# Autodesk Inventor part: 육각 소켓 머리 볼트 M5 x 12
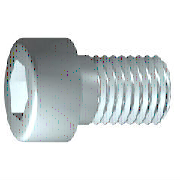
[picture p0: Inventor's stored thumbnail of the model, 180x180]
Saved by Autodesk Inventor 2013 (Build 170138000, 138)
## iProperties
IsCustomPart: 1
Created: 2012-02
Part Number: 육각 소켓 머리 볼트 M5 x 12
Material: 스테인리스강
Description: 6각 소켓 머리 캡 나사
Document SubType Name: Modeling
Standard: ISO 4762
Designer: mdu-01
Standard Revision: Fourth edition 2004-03-01
Standards Organization: ISO
Language: ko-KR
Size Designation: M5 x 12
Categories: <MemberInstance><Categories><Category DisplayName="조임쇠" InternalName="e4da775c-781d-43d5-af7c-5136215cf5a6" Mnemonic="FSTN"><Category DisplayName="볼트" InternalN
Density: 7.75 g/cm^3
Author: mdu-01
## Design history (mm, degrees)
sketch "스케치1"
  geometry: L1 (-1.167, 0)-(12, 0); L2 (12, 0)-(12, 2.5); L3 (12, 2.5)-(2, 2.5); L4 (2, 2.5)-(1.509, 2.5); L5 (1.509, 2.5)-(0, 2.5); L6 (0, 2.5)-(0, 4.25); L7 (0, 4.25)-(-5, 4.25); L8 (-5, 4.25)-(-5, 2.309); L9 (-5, 2.309)-(-2.5, 2.309); L10 (-2.5, 2.309)-(-1.167, 0); L11 (-8.4, 0)-(15.4, 0) reference; L12 (0, -0.85)-(0, 5.1) reference; L13 (2, 2.5)-(0, 2.5)
  constraints: 22 end point, 6 parallel, 2 collinear, 2 perpendicular, 1 horizontal, 1 point on line
  dimensions: "d1" = 10 distance from line of L3.end L2 (= GEL); "d2" = 0.49086 distance of L4.end L3.end (computed from GAL); "d3" = 5 distance between parallel lines of L8 L6 (= KOH); "d4" = 2.5 distance of L8.end L9.end (= INTI); "d5" = 60 deg angle of L10 L1; "d6" = 5 diameter of L3 L1 (= GD); "d7" = 5 diameter of L5 L1 (= BDM); "d8" = 4.6188 diameter of L9 L1 (= 1.1547 x SW); "d9" = 8.5 diameter of L7 L1 (= KOD); "d26" = 12 distance between parallel lines of L12 L2 (= NLG)
revolve "본체" sketch "스케치1" stored, may be unused: angle "d10" = 90 deg
sketch "스케치2"
  geometry: L1 (0, -5.95)-(0, 5.95) reference; L2 (-5.95, 0)-(5.95, 0) reference; L3 (2.309, 0)-(1.155, -2); L4 (1.155, -2)-(-1.155, -2); L5 (-1.155, -2)-(-2.309, 0); L6 (-2.309, 0)-(-1.155, 2); L7 (-1.155, 2)-(1.155, 2); L8 (1.155, 2)-(2.309, 0); 2 further points
  constraints: 12 end point, 1 coincident, 1 horizontal alignment, 1 point on line, 12 other
extrude "슬롯" join sketch "스케치2" stored distance "d11" = 10; taper "d12" = 0 deg
workplane "Work Plane1"
fillet "Fillet2" dims "d30" = 0.05 (= R)
body "Solid1"
fillet "모깎기1" dims "d17" = 0.5 (= RR)
feature "스레드" dims "d13" = 10 (= GEL), "d14" = 0
chamfer "모따기1" distance "d15" = 0.49076 (= -0.5 x SPD + 0.5 x GD); stored, may be unused: second distance "d16" = 0.49076 (= GUL), angle "d27" = 45 deg
other parameters: "GD" = 5 [user parameter; used in 2 equation terms], "NLG" = 12 [user parameter; used in 1 equation term], "GEL" = 10 [user parameter; used in 2 equation terms], "KOD" = 8.5 [user parameter; used in 1 equation term], "KOH" = 5 [user parameter; used in 1 equation term], "INTI" = 2.5 [user parameter; used in 1 equation term], "GAL" = 0.49076 (= 0.61345 x PTC) [user parameter; used in 1 equation term], "GUL" = 0.49076 (= 0.61345 x PTC) [user parameter; used in 1 equation term], "BDM" = 5 (= NND) [user parameter; used in 1 equation term], "SW" = 4 [user parameter; used in 2 equation terms], "RR" = 0.5 [user parameter; used in 1 equation term], "SPD" = 4.01848 (= NND - 1.2269 x PTC) [user parameter; used in 1 equation term], "d19" = 0, "d28" = 0, "d29" = 0, "R" = 0.05 [user parameter; used in 1 equation term], "TOA" = 30 deg [user parameter], "GD1" = 4.01848 (= THREADDIA - 1.2269 x PTC) [user parameter], "THREADDIA" = 5 [user parameter; used in 1 equation term], "FAWI" = 45 deg [user parameter], "TPU" = 12.5 (computed from PTC) [user parameter], "PTC" = 0.8 [user parameter; used in 5 equation terms], "NND" = 5 [user parameter; used in 2 equation terms], "E0" = 4.62 (= 1.155 x SW) [user parameter]
